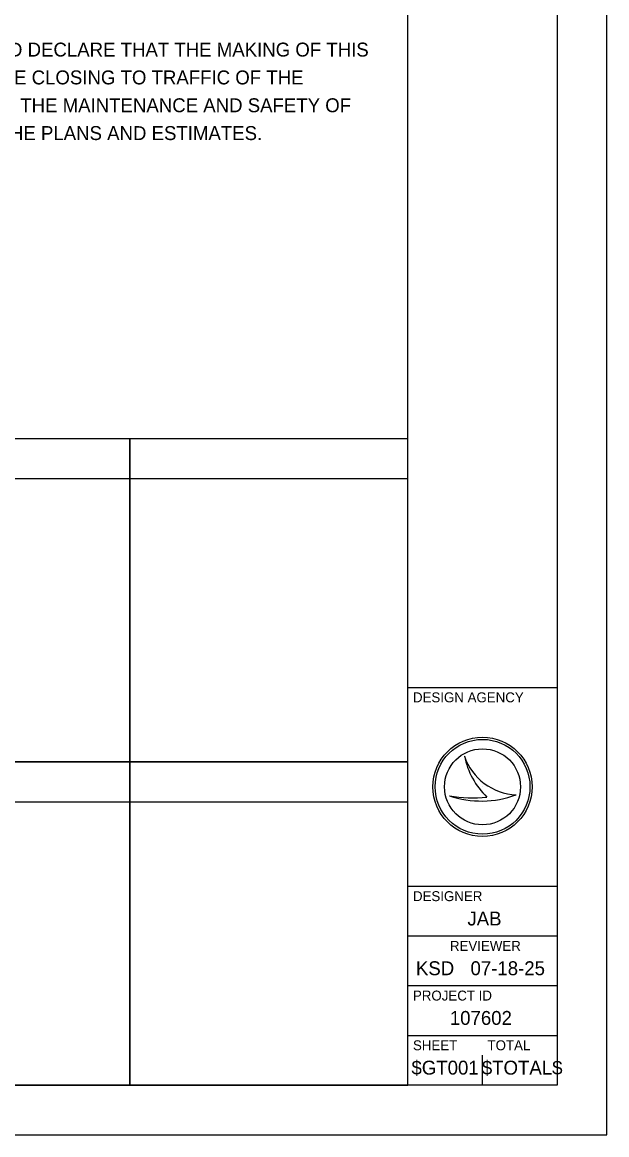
# Model space of a CAD drawing. Extents: x 0 to 34, y 0 to 22.
# Drawn here: x 28.12 to 34, y 0 to 11.19 of the extents above; entities that cross this region are included whole.
import ezdxf

# ---------------------------------------------------------------- set-up
doc = ezdxf.new("R2010")
doc.units = 0
for name, color, linetype in [('SH_Border', 7, 'Continuous'), ('SH_Cut_Line', 7, 'Continuous'), ('SH_Data', 7, 'Continuous'), ('SH_Text', 7, 'Continuous')]:
    doc.layers.add(name, color=color, linetype=linetype)

msp = doc.modelspace()

# ---------------------------------------------------------------- linework, layer by layer
at = {"layer": 'SH_Border'}
for p, q in [((32, 0.5), (32, 21.5)), ((32, 4.5), (33.5, 4.5)), ((32, 2.5), (33.5, 2.5)), ((32, 2), (33.5, 2)), ((32, 1.5), (33.5, 1.5)), ((32, 1), (33.5, 1))]:
    msp.add_line(p, q, dxfattribs=at)
msp.add_lwpolyline([(1.5, 21.5), (33.5, 21.5), (33.5, 0.5), (1.5, 0.5)], close=True, dxfattribs=at)
at = {"layer": 'SH_Cut_Line'}
msp.add_lwpolyline([(0, 0), (34, 0), (34, 22), (0, 22)], close=True, dxfattribs=at)
at = {"layer": 'SH_Data'}
for p, q in [((26.4, 6.6), (29.2, 6.6)), ((29.2, 6.6), (32, 6.6)), ((32.567, 3.81), (32.567, 3.81)), ((32.75, 3.5), (32.75, 3.5)), ((32.417, 3.41), (32.417, 3.41)), ((33.087, 3.419), (33.087, 3.419)), ((26.4, 3.35), (29.2, 3.35)), ((29.2, 3.35), (32, 3.35)), ((32.75, 0.5), (32.75, 0.8)), ((32.375, 0.675), (32.375, 0.675))]:
    msp.add_line(p, q, dxfattribs=at)
for points in [[(29.2, 7), (26.4, 7), (26.4, 3.75), (29.2, 3.75)], [(32, 7), (29.2, 7), (29.2, 3.75), (32, 3.75)], [(29.2, 3.75), (26.4, 3.75), (26.4, 0.5), (29.2, 0.5)], [(32, 3.75), (29.2, 3.75), (29.2, 0.5), (32, 0.5)]]:
    msp.add_lwpolyline(points, close=True, dxfattribs=at)
for radius in [0.5, 0.477, 0.477, 0.382]:
    msp.add_circle((32.75, 3.5), radius, dxfattribs=at)
for centre, radius, start, end in [((33.116, 3.998), 0.58, 198.9257, 198.9319), ((33.347, 3.97), 0.796, 191.6379, 191.6421), ((33.116, 3.998), 0.58, 198.9319, 267.1657), ((33.347, 3.97), 0.796, 191.6421, 226.0947), ((32.739, 4.37), 1.013, 251.4576, 290.0832), ((32.648, 4.654), 1.266, 259.4964, 259.4995), ((32.739, 4.37), 1.013, 251.4527, 251.4576), ((32.648, 4.654), 1.266, 259.4995, 276.6672)]:
    msp.add_arc(centre, radius, start, end, dxfattribs=at)

# ---------------------------------------------------------------- texts
for s, height, p in [('DESIGN AGENCY', 0.1, (32.05, 4.35)), ('DESIGNER', 0.1, (32.05, 2.35)), ('JAB', 0.14, (32.598, 2.105)), ('REVIEWER', 0.1, (32.422, 1.85)), ('KSD', 0.14, (32.08, 1.605)), ('07-18-25', 0.14, (32.629, 1.605)), ('PROJECT ID', 0.1, (32.05, 1.35)), ('107602', 0.14, (32.421, 1.105)), ('SHEET', 0.1, (32.05, 0.85)), ('TOTAL', 0.1, (32.8, 0.85)), ('$GT001', 0.14, (32.035, 0.605)), ('$TOTAL$', 0.14, (32.743, 0.605))]:
    msp.add_text(s, height=height, dxfattribs=at).set_placement(p)
at = {"layer": 'SH_Text'}
for s, p in [('I HEREBY APPROVE THESE PLANS AND DECLARE THAT THE MAKING OF THIS ', (24.5, 10.846)), ('IMPROVEMENT WILL NOT REQUIRE THE CLOSING TO TRAFFIC OF THE ', (24.5, 10.566)), ('HIGHWAY AND THAT PROVISIONS FOR THE MAINTENANCE AND SAFETY OF ', (24.5, 10.286)), ('TRAFFIC WILL BE AS SET FORTH ON THE PLANS AND ESTIMATES.', (24.5, 10.006))]:
    msp.add_text(s, height=0.14, dxfattribs=at).set_placement(p)

doc.saveas('drawing.dxf')
